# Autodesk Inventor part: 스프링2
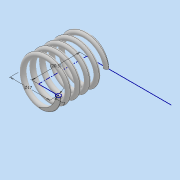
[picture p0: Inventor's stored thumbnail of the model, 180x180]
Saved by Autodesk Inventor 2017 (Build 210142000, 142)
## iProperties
Part Number: 스프링2
Material: 일반
Document SubType Name: Modeling
Designer: MRC
Density: 1 g/cm^3
Appearance: 기본값
Mass: 0.821961 g
Surface Area: 16.7185 cm^2
Volume: 0.821961 cm^3
Author: MRC
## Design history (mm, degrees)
sketch "스케치1"
  geometry: L1 (0, 0)-(0, 20.5); L2 (0, 0)-(8.5, 0); L3 (0, 20.5)-(36.027, 20.5); C1 r 1 at (8.5, 0)
  constraints: 6 end point, 2 horizontal, 1 centre point, 1 coincident, 1 vertical
  dimensions: "d0" = 20.5 distance of L1.start L1.end (derived); "d2" = 2 diameter of C1; "d3" = 17 diameter of L2.end L1
feature "코일1" pitch "d4" = 10; turns "d6" = 5; dims "d5" = 20.5 (= d0), "d7" = 0, angle "d8" = 90 deg, angle "d9" = 90 deg, "d10" = 0, "d11" = 0
sketch "스케치2"
  geometry: L1 (20.5, 10)-(0, 10); L2 (0, 10)-(0, -10); L3 (0, -10)-(20.5, -10); L4 (20.5, -10)-(20.5, 10); 2 further points
  constraints: 8 end point, 2 parallel, 1 coincident, 1 horizontal, 1 midpoint, 1 perpendicular
  dimensions: "d12" = 20 distance of L3.end L1.start; "d13" = 20.5 distance of L2.end L3.end (= d0)
extrude "돌출1" sketch "스케치2" stored distance "d14" = 0; taper "d15" = 0 deg
node "솔리드1"
